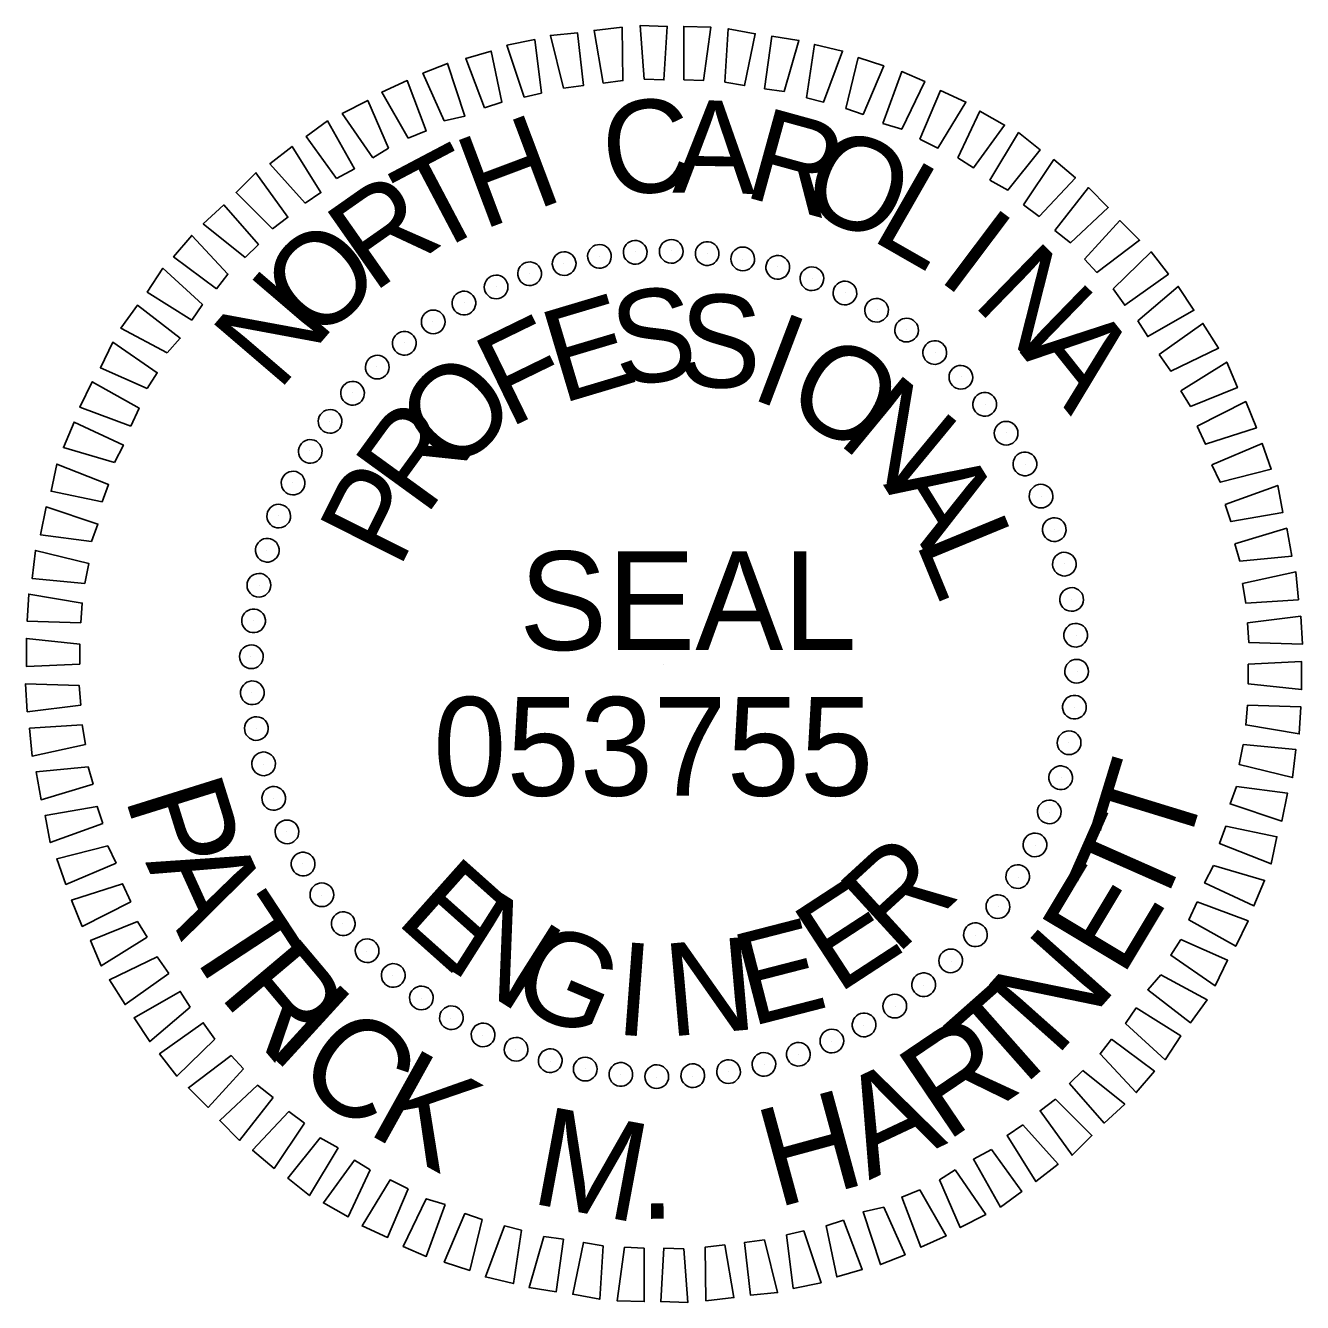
# Model space of a CAD drawing. Extents: x 1184121 to 1184397, y 1246506 to 1246661.
# Drawn here: x 1184386.64 to 1184396.53, y 1246611.29 to 1246621.18 of the extents above; entities that cross this region are included whole.
import ezdxf

# ---------------------------------------------------------------- set-up
doc = ezdxf.new("R2010")
doc.units = 0
doc.layers.add('Sheet PE Seal Cell', color=7, linetype='Continuous')

msp = doc.modelspace()

# ---------------------------------------------------------------- linework, layer by layer
at = {"layer": 'Sheet PE Seal Cell'}
for p, q in [((1184391.0892, 1246619.3869), (1184391.0892, 1246619.3869)), ((1184391.363, 1246619.4251), (1184391.363, 1246619.4251)), ((1184391.6431, 1246619.4314), (1184391.6431, 1246619.4314)), ((1184391.9233, 1246619.4123), (1184391.9233, 1246619.4123)), ((1184392.1971, 1246619.3678), (1184392.1971, 1246619.3678)), ((1184390.809, 1246619.3359), (1184390.809, 1246619.3359)), ((1184392.4645, 1246619.3105), (1184392.4645, 1246619.3105)), ((1184390.5416, 1246619.2595), (1184390.5416, 1246619.2595)), ((1184392.7319, 1246619.2213), (1184392.7319, 1246619.2213)), ((1184390.2869, 1246619.1576), (1184390.2869, 1246619.1576)), ((1184392.9866, 1246619.1067), (1184392.9866, 1246619.1067)), ((1184390.0386, 1246619.0303), (1184390.0386, 1246619.0303)), ((1184393.235, 1246618.9794), (1184393.235, 1246618.9794)), ((1184389.7966, 1246618.8838), (1184389.7966, 1246618.8838)), ((1184393.4642, 1246618.8202), (1184393.4642, 1246618.8202)), ((1184389.5737, 1246618.7247), (1184389.5737, 1246618.7247)), ((1184393.6871, 1246618.6483), (1184393.6871, 1246618.6483)), ((1184389.3636, 1246618.5336), (1184389.3636, 1246618.5336)), ((1184393.8844, 1246618.4572), (1184393.8844, 1246618.4572)), ((1184389.1726, 1246618.3363), (1184389.1726, 1246618.3363)), ((1184394.0755, 1246618.2471), (1184394.0755, 1246618.2471)), ((1184389.0007, 1246618.1134), (1184389.0007, 1246618.1134)), ((1184394.2346, 1246618.0243), (1184394.2346, 1246618.0243)), ((1184388.8415, 1246617.8842), (1184388.8415, 1246617.8842)), ((1184394.3811, 1246617.7823), (1184394.3811, 1246617.7823)), ((1184388.7141, 1246617.6358), (1184388.7141, 1246617.6358)), ((1184394.5084, 1246617.534), (1184394.5084, 1246617.534)), ((1184388.5995, 1246617.3812), (1184388.5995, 1246617.3812)), ((1184394.6103, 1246617.2793), (1184394.6103, 1246617.2793)), ((1184388.5104, 1246617.1137), (1184388.5104, 1246617.1137)), ((1184394.6867, 1246617.0118), (1184394.6867, 1246617.0118)), ((1184388.4531, 1246616.8463), (1184388.4531, 1246616.8463)), ((1184394.7377, 1246616.7317), (1184394.7377, 1246616.7317)), ((1184388.4085, 1246616.5725), (1184388.4085, 1246616.5725)), ((1184394.7759, 1246616.4579), (1184394.7759, 1246616.4579)), ((1184388.3894, 1246616.2923), (1184388.3894, 1246616.2923)), ((1184391.5858, 1246616.235), (1184391.5858, 1246616.235)), ((1184394.7822, 1246616.1777), (1184394.7822, 1246616.1777)), ((1184388.3958, 1246616.0122), (1184388.3958, 1246616.0122)), ((1184394.7631, 1246615.8976), (1184394.7631, 1246615.8976)), ((1184388.434, 1246615.7384), (1184388.434, 1246615.7384)), ((1184394.7186, 1246615.6238), (1184394.7186, 1246615.6238)), ((1184388.4849, 1246615.4582), (1184388.4849, 1246615.4582)), ((1184394.6613, 1246615.3563), (1184394.6613, 1246615.3563)), ((1184388.5613, 1246615.1908), (1184388.5613, 1246615.1908)), ((1184394.5721, 1246615.0889), (1184394.5721, 1246615.0889)), ((1184388.6632, 1246614.9361), (1184388.6632, 1246614.9361)), ((1184394.4575, 1246614.8342), (1184394.4575, 1246614.8342)), ((1184388.7906, 1246614.6878), (1184388.7906, 1246614.6878)), ((1184394.3302, 1246614.5859), (1184394.3302, 1246614.5859)), ((1184388.937, 1246614.4458), (1184388.937, 1246614.4458)), ((1184394.171, 1246614.3567), (1184394.171, 1246614.3567)), ((1184389.0962, 1246614.2229), (1184389.0962, 1246614.2229)), ((1184393.9991, 1246614.1338), (1184393.9991, 1246614.1338)), ((1184389.2872, 1246614.0128), (1184389.2872, 1246614.0128)), ((1184393.808, 1246613.9364), (1184393.808, 1246613.9364)), ((1184389.4846, 1246613.8218), (1184389.4846, 1246613.8218)), ((1184393.5979, 1246613.7454), (1184393.5979, 1246613.7454)), ((1184389.7075, 1246613.6499), (1184389.7075, 1246613.6499)), ((1184393.3751, 1246613.5862), (1184393.3751, 1246613.5862)), ((1184389.9367, 1246613.4907), (1184389.9367, 1246613.4907)), ((1184393.1331, 1246613.4398), (1184393.1331, 1246613.4398)), ((1184390.185, 1246613.3633), (1184390.185, 1246613.3633)), ((1184390.4397, 1246613.2487), (1184390.4397, 1246613.2487)), ((1184392.8848, 1246613.3124), (1184392.8848, 1246613.3124)), ((1184390.7071, 1246613.1596), (1184390.7071, 1246613.1596)), ((1184392.3626, 1246613.1341), (1184392.3626, 1246613.1341)), ((1184392.6301, 1246613.2105), (1184392.6301, 1246613.2105)), ((1184390.9746, 1246613.1023), (1184390.9746, 1246613.1023)), ((1184391.2484, 1246613.0577), (1184391.2484, 1246613.0577)), ((1184391.5285, 1246613.0386), (1184391.5285, 1246613.0386)), ((1184391.8087, 1246613.045), (1184391.8087, 1246613.045)), ((1184392.0825, 1246613.0832), (1184392.0825, 1246613.0832))]:
    msp.add_line(p, q, dxfattribs=at)
for points in [[(1184391.1146, 1246620.7304), (1184391.0446, 1246621.1379), (1184391.2611, 1246621.1634), (1184391.2675, 1246620.7495)], [(1184391.433, 1246620.7622), (1184391.4012, 1246621.1761), (1184391.6113, 1246621.1697), (1184391.5858, 1246620.7558)], [(1184391.7386, 1246620.7558), (1184391.7386, 1246621.1697), (1184391.9488, 1246621.1634), (1184391.8915, 1246620.7495)], [(1184392.057, 1246620.7367), (1184392.0825, 1246621.1506), (1184392.2926, 1246621.1124), (1184392.2098, 1246620.7113)], [(1184390.5034, 1246620.6221), (1184390.3697, 1246621.0233), (1184390.5861, 1246621.0679), (1184390.6371, 1246620.654)], [(1184390.809, 1246620.6922), (1184390.7071, 1246621.0997), (1184390.9173, 1246621.1188), (1184390.9618, 1246620.7113)], [(1184392.3626, 1246620.6858), (1184392.4199, 1246621.0933), (1184392.6301, 1246621.0615), (1184392.5155, 1246620.6667)], [(1184390.1977, 1246620.5394), (1184390.0513, 1246620.9214), (1184390.2487, 1246620.9787), (1184390.3315, 1246620.5839)], [(1184392.6874, 1246620.6158), (1184392.7511, 1246621.0296), (1184392.9675, 1246620.9787), (1184392.8211, 1246620.5839)], [(1184389.8857, 1246620.4375), (1184389.7202, 1246620.8068), (1184389.9112, 1246620.8832), (1184390.0449, 1246620.4757)], [(1184392.993, 1246620.533), (1184393.0885, 1246620.9278), (1184393.2859, 1246620.8641), (1184393.1267, 1246620.4884)], [(1184389.6056, 1246620.3038), (1184389.4018, 1246620.6603), (1184389.5992, 1246620.7495), (1184389.7457, 1246620.3611)], [(1184393.2795, 1246620.4184), (1184393.426, 1246620.8195), (1184393.6043, 1246620.7431), (1184393.426, 1246620.3738)], [(1184393.5661, 1246620.2974), (1184393.7253, 1246620.6731), (1184393.9226, 1246620.5839), (1184393.7062, 1246620.2274)], [(1184389.3318, 1246620.151), (1184389.0962, 1246620.4948), (1184389.2936, 1246620.5967), (1184389.4528, 1246620.2274)], [(1184393.859, 1246620.151), (1184394.0309, 1246620.5139), (1184394.2219, 1246620.4056), (1184393.98, 1246620.0745)], [(1184389.0516, 1246619.9918), (1184388.816, 1246620.3165), (1184388.9816, 1246620.4375), (1184389.1917, 1246620.0682)], [(1184394.1073, 1246619.979), (1184394.3302, 1246620.3483), (1184394.4957, 1246620.2146), (1184394.2474, 1246619.9026)], [(1184388.8097, 1246619.8007), (1184388.5359, 1246620.1064), (1184388.7078, 1246620.2401), (1184388.9306, 1246619.8835)], [(1184394.3684, 1246619.788), (1184394.604, 1246620.1382), (1184394.7695, 1246619.9981), (1184394.4893, 1246619.6989)], [(1184388.555, 1246619.6034), (1184388.2748, 1246619.8835), (1184388.4276, 1246620.0363), (1184388.6759, 1246619.6925)], [(1184394.6103, 1246619.5906), (1184394.8714, 1246619.9217), (1184395.0242, 1246619.7689), (1184394.7313, 1246619.4951)], [(1184388.3448, 1246619.3805), (1184388.0201, 1246619.6416), (1184388.1793, 1246619.788), (1184388.4467, 1246619.4824)], [(1184394.8395, 1246619.3678), (1184395.1133, 1246619.667), (1184395.2662, 1246619.5142), (1184394.9351, 1246619.2659)], [(1184388.122, 1246619.1385), (1184387.7909, 1246619.3869), (1184387.931, 1246619.5524), (1184388.2111, 1246619.2532)], [(1184395.0624, 1246619.1385), (1184395.3553, 1246619.4251), (1184395.489, 1246619.2532), (1184395.1515, 1246619.0112)], [(1184387.931, 1246618.8966), (1184387.5871, 1246619.1131), (1184387.7081, 1246619.2977), (1184388.0137, 1246619.0176)], [(1184395.2534, 1246618.8902), (1184395.5654, 1246619.1576), (1184395.6864, 1246618.973), (1184395.3298, 1246618.7692)], [(1184387.7399, 1246618.6419), (1184387.3834, 1246618.8329), (1184387.5107, 1246619.0112), (1184387.8418, 1246618.7565)], [(1184395.419, 1246618.6292), (1184395.7564, 1246618.8711), (1184395.8774, 1246618.6801), (1184395.5081, 1246618.5018)], [(1184387.5871, 1246618.3681), (1184387.2242, 1246618.5273), (1184387.3197, 1246618.7247), (1184387.6635, 1246618.4891)], [(1184395.5845, 1246618.349), (1184395.9411, 1246618.5718), (1184396.0239, 1246618.3745), (1184395.6609, 1246618.228)], [(1184387.4598, 1246618.0752), (1184387.065, 1246618.2216), (1184387.1605, 1246618.419), (1184387.5235, 1246618.2153)], [(1184395.7119, 1246618.0752), (1184396.0875, 1246618.2662), (1184396.1703, 1246618.0625), (1184395.7755, 1246617.9351)], [(1184387.3324, 1246617.795), (1184386.9377, 1246617.9096), (1184387.0204, 1246618.107), (1184387.4025, 1246617.9287)], [(1184395.8265, 1246617.7759), (1184396.2149, 1246617.9415), (1184396.2849, 1246617.7441), (1184395.8902, 1246617.6422)], [(1184387.2369, 1246617.4894), (1184386.8421, 1246617.5722), (1184386.8867, 1246617.7823), (1184387.2879, 1246617.6231)], [(1184395.9284, 1246617.4703), (1184396.3359, 1246617.6167), (1184396.3741, 1246617.4066), (1184395.9729, 1246617.3366)], [(1184387.1541, 1246617.1838), (1184386.7594, 1246617.2347), (1184386.8039, 1246617.4512), (1184387.2051, 1246617.3175)], [(1184396.0048, 1246617.1647), (1184396.4059, 1246617.2856), (1184396.4441, 1246617.0692), (1184396.043, 1246617.0309)], [(1184387.1032, 1246616.859), (1184386.6957, 1246616.8972), (1184386.7212, 1246617.1137), (1184387.135, 1246617.0118)], [(1184396.0621, 1246616.859), (1184396.476, 1246616.9482), (1184396.4951, 1246616.7317), (1184396.0875, 1246616.7062)], [(1184387.0714, 1246616.5534), (1184386.6575, 1246616.5661), (1184386.6702, 1246616.7763), (1184387.0841, 1246616.7062)], [(1184396.1003, 1246616.5534), (1184396.5142, 1246616.6043), (1184396.5269, 1246616.3878), (1184396.113, 1246616.4006)], [(1184387.065, 1246616.235), (1184386.6511, 1246616.2159), (1184386.6511, 1246616.4324), (1184387.065, 1246616.3878)], [(1184396.1066, 1246616.235), (1184396.5205, 1246616.2541), (1184396.5205, 1246616.0376), (1184396.1066, 1246616.0822)], [(1184387.0714, 1246615.9167), (1184386.6575, 1246615.8657), (1184386.6448, 1246616.0822), (1184387.0586, 1246616.0695)], [(1184396.1003, 1246615.9167), (1184396.5142, 1246615.9039), (1184396.5014, 1246615.6938), (1184396.0875, 1246615.7638)], [(1184387.1096, 1246615.611), (1184386.6957, 1246615.5219), (1184386.6766, 1246615.7384), (1184387.0841, 1246615.7638)], [(1184396.0684, 1246615.611), (1184396.476, 1246615.5728), (1184396.4505, 1246615.3563), (1184396.0366, 1246615.4582)], [(1184387.1669, 1246615.3054), (1184386.7657, 1246615.1844), (1184386.7275, 1246615.4009), (1184387.1287, 1246615.4391)], [(1184396.0175, 1246615.2863), (1184396.4123, 1246615.2354), (1184396.3677, 1246615.0189), (1184395.9666, 1246615.1526)], [(1184387.2433, 1246614.9998), (1184386.8358, 1246614.8533), (1184386.7976, 1246615.0634), (1184387.1987, 1246615.1335)], [(1184395.9347, 1246614.9807), (1184396.3295, 1246614.8979), (1184396.2849, 1246614.6878), (1184395.8838, 1246614.8469)], [(1184387.3452, 1246614.6941), (1184386.9568, 1246614.5286), (1184386.8867, 1246614.726), (1184387.2815, 1246614.8278)], [(1184395.8392, 1246614.675), (1184396.234, 1246614.5604), (1184396.1512, 1246614.363), (1184395.7692, 1246614.5413)], [(1184387.4598, 1246614.3949), (1184387.0841, 1246614.2038), (1184387.0013, 1246614.4076), (1184387.3961, 1246614.5349)], [(1184395.7119, 1246614.3949), (1184396.1066, 1246614.2484), (1184396.0111, 1246614.051), (1184395.6482, 1246614.2548)], [(1184387.5871, 1246614.1211), (1184387.2306, 1246613.8982), (1184387.1478, 1246614.0956), (1184387.5107, 1246614.242)], [(1184395.5845, 1246614.102), (1184395.9475, 1246613.9428), (1184395.852, 1246613.7454), (1184395.5081, 1246613.981)], [(1184387.7527, 1246613.8409), (1184387.4152, 1246613.5989), (1184387.2942, 1246613.79), (1184387.6635, 1246613.9682)], [(1184395.4317, 1246613.8282), (1184395.7883, 1246613.6371), (1184395.6609, 1246613.4589), (1184395.3298, 1246613.7136)], [(1184387.9182, 1246613.5798), (1184387.6062, 1246613.3124), (1184387.4852, 1246613.4971), (1184387.8418, 1246613.7008)], [(1184395.2407, 1246613.5735), (1184395.5845, 1246613.357), (1184395.4635, 1246613.1723), (1184395.1579, 1246613.4525)], [(1184388.1092, 1246613.3315), (1184387.8163, 1246613.045), (1184387.6826, 1246613.2169), (1184388.0201, 1246613.4589)], [(1184395.0497, 1246613.3315), (1184395.3808, 1246613.0832), (1184395.2407, 1246612.9176), (1184394.9605, 1246613.2169)], [(1184388.3321, 1246613.1023), (1184388.0583, 1246612.803), (1184387.9055, 1246612.9558), (1184388.2366, 1246613.2042)], [(1184394.8268, 1246613.0896), (1184395.1515, 1246612.8285), (1184394.9924, 1246612.682), (1184394.7249, 1246612.9877)], [(1184388.5613, 1246612.8794), (1184388.3003, 1246612.5483), (1184388.1475, 1246612.7011), (1184388.4404, 1246612.9749)], [(1184394.6167, 1246612.8667), (1184394.8969, 1246612.5865), (1184394.744, 1246612.4337), (1184394.4957, 1246612.7776)], [(1184388.8033, 1246612.682), (1184388.5677, 1246612.3318), (1184388.4021, 1246612.4719), (1184388.6823, 1246612.7712)], [(1184394.362, 1246612.6693), (1184394.6358, 1246612.3637), (1184394.4639, 1246612.23), (1184394.241, 1246612.5865)], [(1184389.0644, 1246612.491), (1184388.8415, 1246612.1217), (1184388.6759, 1246612.2554), (1184388.9243, 1246612.5674)], [(1184394.12, 1246612.4783), (1184394.3556, 1246612.1536), (1184394.1901, 1246612.0326), (1184393.98, 1246612.4019)], [(1184389.3127, 1246612.3191), (1184389.1408, 1246611.9562), (1184388.9497, 1246612.0644), (1184389.1917, 1246612.3955)], [(1184393.8399, 1246612.3191), (1184394.0755, 1246611.9753), (1184393.8781, 1246611.8734), (1184393.7189, 1246612.2427)], [(1184389.6056, 1246612.1727), (1184389.4464, 1246611.797), (1184389.249, 1246611.8861), (1184389.4655, 1246612.2427)], [(1184393.5661, 1246612.1663), (1184393.7698, 1246611.8097), (1184393.5724, 1246611.7206), (1184393.426, 1246612.109)], [(1184389.8921, 1246612.0517), (1184389.7457, 1246611.6505), (1184389.5674, 1246611.7269), (1184389.7457, 1246612.0962)], [(1184390.1786, 1246611.9371), (1184390.0831, 1246611.5423), (1184389.8857, 1246611.606), (1184390.0449, 1246611.9816)], [(1184393.2859, 1246612.0326), (1184393.4515, 1246611.6633), (1184393.2604, 1246611.5869), (1184393.1267, 1246611.9944)], [(1184390.4843, 1246611.8543), (1184390.4206, 1246611.4404), (1184390.2041, 1246611.4913), (1184390.3506, 1246611.8861)], [(1184392.9739, 1246611.9307), (1184393.1204, 1246611.5487), (1184392.923, 1246611.4913), (1184392.8402, 1246611.8861)], [(1184390.809, 1246611.7842), (1184390.7517, 1246611.3767), (1184390.5416, 1246611.4086), (1184390.6562, 1246611.8033)], [(1184391.1146, 1246611.7333), (1184391.0892, 1246611.3194), (1184390.879, 1246611.3576), (1184390.9618, 1246611.7588)], [(1184392.3626, 1246611.7779), (1184392.4645, 1246611.3704), (1184392.2544, 1246611.3513), (1184392.2098, 1246611.7588)], [(1184392.6683, 1246611.8479), (1184392.802, 1246611.4468), (1184392.5855, 1246611.4022), (1184392.5346, 1246611.8161)], [(1184391.433, 1246611.7142), (1184391.433, 1246611.3003), (1184391.2229, 1246611.3067), (1184391.2802, 1246611.7206)], [(1184391.7386, 1246611.7078), (1184391.7705, 1246611.294), (1184391.5604, 1246611.3003), (1184391.5858, 1246611.7142)], [(1184392.057, 1246611.7397), (1184392.1271, 1246611.3322), (1184391.9106, 1246611.3067), (1184391.9042, 1246611.7206)]]:
    msp.add_lwpolyline(points, close=True, dxfattribs=at)
for centre, major_axis in [((1184391.0862, 1246619.3896), (-0.0143, 0.0906)), ((1184391.363, 1246619.4211), (-0.0064, 0.0915)), ((1184391.6416, 1246619.4284), (0.0016, 0.0917)), ((1184391.9197, 1246619.4114), (0.0096, 0.0912)), ((1184392.1952, 1246619.3702), (0.0175, 0.09)), ((1184390.8132, 1246619.334), (-0.0222, 0.089)), ((1184392.4662, 1246619.3052), (0.0253, 0.0881)), ((1184390.546, 1246619.2549), (-0.0299, 0.0867)), ((1184392.7304, 1246619.2168), (0.0329, 0.0856)), ((1184390.2868, 1246619.1528), (-0.0373, 0.0838)), ((1184392.9859, 1246619.1057), (0.0402, 0.0824)), ((1184390.0374, 1246619.0284), (-0.0445, 0.0802)), ((1184393.2308, 1246618.9727), (0.0472, 0.0786)), ((1184389.7998, 1246618.8829), (-0.0513, 0.076)), ((1184393.4631, 1246618.8189), (0.0539, 0.0742)), ((1184389.5759, 1246618.7171), (-0.0577, 0.0713)), ((1184393.6812, 1246618.6455), (0.0602, 0.0692)), ((1184389.3672, 1246618.5325), (-0.0637, 0.066)), ((1184393.8833, 1246618.4537), (0.066, 0.0637)), ((1184389.1754, 1246618.3304), (-0.0692, 0.0602)), ((1184394.0679, 1246618.245), (0.0713, 0.0577)), ((1184389.0019, 1246618.1123), (-0.0742, 0.0539)), ((1184394.2337, 1246618.021), (0.076, 0.0513)), ((1184388.8481, 1246617.88), (-0.0786, 0.0472)), ((1184394.3792, 1246617.7834), (0.0802, 0.0445)), ((1184388.7152, 1246617.6351), (-0.0824, 0.0402)), ((1184394.5036, 1246617.5341), (0.0838, 0.0373)), ((1184388.6041, 1246617.3796), (-0.0856, 0.0329)), ((1184394.6057, 1246617.2748), (0.0867, 0.0299)), ((1184388.5157, 1246617.1154), (-0.0881, 0.0253)), ((1184394.6848, 1246617.0077), (0.089, 0.0222)), ((1184388.4506, 1246616.8444), (-0.09, 0.0175)), ((1184394.7404, 1246616.7347), (0.0906, 0.0143)), ((1184388.4095, 1246616.5689), (-0.0912, 0.0096)), ((1184394.7719, 1246616.4578), (0.0915, 0.0064)), ((1184388.3924, 1246616.2908), (-0.0917, 0.0016)), ((1184394.7792, 1246616.1793), (0.0917, -0.0016)), ((1184388.3997, 1246616.0122), (-0.0915, -0.0064)), ((1184394.7622, 1246615.9012), (0.0912, -0.0096)), ((1184388.4313, 1246615.7354), (-0.0906, -0.0143)), ((1184394.721, 1246615.6256), (0.09, -0.0175)), ((1184388.4868, 1246615.4624), (-0.089, -0.0222)), ((1184394.656, 1246615.3547), (0.0881, -0.0253)), ((1184388.566, 1246615.1952), (-0.0867, -0.0299)), ((1184394.5676, 1246615.0904), (0.0856, -0.0329)), ((1184388.6681, 1246614.936), (-0.0838, -0.0373)), ((1184394.4565, 1246614.8349), (0.0824, -0.0402)), ((1184388.7924, 1246614.6866), (-0.0802, -0.0445)), ((1184394.3235, 1246614.5901), (0.0786, -0.0472)), ((1184388.938, 1246614.449), (-0.076, -0.0513)), ((1184394.1697, 1246614.3577), (0.0742, -0.0539)), ((1184389.1037, 1246614.2251), (-0.0713, -0.0577)), ((1184393.9963, 1246614.1397), (0.0692, -0.0602)), ((1184389.2883, 1246614.0164), (-0.066, -0.0637)), ((1184393.8045, 1246613.9376), (0.0637, -0.066)), ((1184389.4905, 1246613.8246), (-0.0602, -0.0692)), ((1184393.5958, 1246613.7529), (0.0577, -0.0713)), ((1184389.7085, 1246613.6511), (-0.0539, -0.0742)), ((1184393.3718, 1246613.5872), (0.0513, -0.076)), ((1184389.9409, 1246613.4973), (-0.0472, -0.0786)), ((1184393.1342, 1246613.4416), (0.0445, -0.0802)), ((1184390.1857, 1246613.3644), (-0.0402, -0.0824)), ((1184390.4412, 1246613.2533), (-0.0329, -0.0856)), ((1184392.8849, 1246613.3173), (0.0373, -0.0838)), ((1184390.7055, 1246613.1649), (-0.0253, -0.0881)), ((1184392.3585, 1246613.136), (0.0222, -0.089)), ((1184392.6256, 1246613.2152), (0.0299, -0.0867)), ((1184390.9764, 1246613.0998), (-0.0175, -0.09)), ((1184391.252, 1246613.0587), (-0.0096, -0.0912)), ((1184391.5301, 1246613.0416), (-0.0016, -0.0917)), ((1184391.8086, 1246613.0489), (0.0064, -0.0915)), ((1184392.0855, 1246613.0805), (0.0143, -0.0906))]:
    msp.add_ellipse(centre, major_axis=major_axis, ratio=0.999708, dxfattribs=at)

# ---------------------------------------------------------------- texts
for s, height, rotation, p in [('C', 0.718, 6.21987, (1184391.1465, 1246619.8453)), ('A', 0.7179, 359.02032, (1184391.6495, 1246619.8835)), ('H', 0.718, 20.61948, (1184390.1786, 1246619.5906)), ('R', 0.718, 344.6211, (1184392.1844, 1246619.8581)), ('O', 0.718, 337.42116, (1184392.611, 1246619.7625)), ('T', 0.718, 27.81977, (1184389.7648, 1246619.3805)), ('L', 0.718, 330.22088, (1184393.1713, 1246619.5269)), ('R', 0.718, 35.02051, (1184389.3318, 1246619.1003)), ('I', 0.7179, 323.02014, (1184393.6871, 1246619.2213)), ('O', 0.718, 42.22174, (1184388.8924, 1246618.7056)), ('N', 0.7181, 315.81891, (1184393.9608, 1246619.0239)), ('N', 0.7181, 49.4235, (1184388.5995, 1246618.3363)), ('E', 0.718, 16.61107, (1184390.7899, 1246618.2471)), ('S', 0.718, 7.25561, (1184391.2293, 1246618.3808)), ('S', 0.718, 357.9004, (1184391.6877, 1246618.3872)), ('F', 0.7179, 25.96703, (1184390.3824, 1246618.0561)), ('I', 0.718, 339.1896, (1184392.2353, 1246618.2981)), ('A', 0.7181, 308.61715, (1184394.3365, 1246618.6483)), ('O', 0.718, 329.83348, (1184392.49, 1246618.2089)), ('O', 0.7181, 44.68124, (1184389.9621, 1246617.6804)), ('N', 0.718, 320.47661, (1184392.9166, 1246617.9542)), ('R', 0.7181, 54.03965, (1184389.7393, 1246617.3684)), ('P', 0.7182, 63.39889, (1184389.5355, 1246616.9609)), ('A', 0.7181, 301.76027, (1184393.2795, 1246617.6231)), ('L', 0.7182, 292.40085, (1184393.5279, 1246617.1838)), ('SEAL', 0.76385, 360, (1184390.4653, 1246616.3431)), ('T', 0.7639, 72.95572, (1184395.611, 1246614.7225)), ('P', 0.7639, 287.35338, (1184387.4101, 1246615.2091)), ('T', 0.7639, 66.15549, (1184395.4035, 1246614.2566)), ('R', 0.7181, 42.48141, (1184393.3814, 1246613.9746)), ('A', 0.7639, 294.46272, (1184387.5692, 1246614.7002)), ('E', 0.718, 318.27689, (1184389.4973, 1246614.242)), ('E', 0.7639, 59.04615, (1184395.1293, 1246613.7993)), ('E', 0.718, 33.12409, (1184392.9293, 1246613.6753)), ('T', 0.7639, 303.30302, (1184387.8527, 1246614.1011)), ('N', 0.718, 327.63396, (1184389.8794, 1246613.8982)), ('E', 0.718, 14.41176, (1184392.2544, 1246613.427)), ('G', 0.718, 336.99024, (1184390.3633, 1246613.6117)), ('N', 0.7639, 48.32032, (1184394.6141, 1246613.1824)), ('R', 0.7639, 310.10326, (1184388.1317, 1246613.6741)), ('I', 0.718, 355.7012, (1184391.1974, 1246613.3697)), ('N', 0.718, 5.05639, (1184391.624, 1246613.3506)), ('I', 0.7639, 317.58352, (1184388.4945, 1246613.2462)), ('T', 0.7639, 41.52008, (1184394.2313, 1246612.8453)), ('C', 0.7639, 321.38547, (1184388.6994, 1246613.0478)), ('R', 0.7639, 34.03982, (1184393.7675, 1246612.5297)), ('K', 0.7639, 330.96762, (1184389.2703, 1246612.6118)), ('A', 0.7639, 25.19951, (1184393.1722, 1246612.2384)), ('H', 0.7639, 15.21553, (1184392.4553, 1246612.0239)), ('M', 0.7639, 349.45191, (1184390.5384, 1246612.0646)), ('.', 0.7639, 0.9814, (1184391.3931, 1246611.9394))]:
    msp.add_text(s, height=height, rotation=rotation, dxfattribs=at).set_placement(p)
msp.add_text('053755', height=0.76385, dxfattribs=at).set_placement((1184389.7983, 1246615.2152))

doc.saveas('drawing.dxf')
